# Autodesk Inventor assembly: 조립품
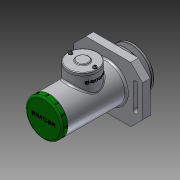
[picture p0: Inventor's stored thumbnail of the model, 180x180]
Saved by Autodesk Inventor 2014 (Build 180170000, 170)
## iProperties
Created: 2017-10
Part Number: 조립품
Document SubType Name: Assembly
Designer: NET
Author: NET
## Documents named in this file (20)
- C:\Users\NET\Desktop\471007V1020\조립품.iam
- C:\Users\NET\Desktop\471007V1020\본체.ipt
- C:\Users\NET\Desktop\471007V1020\사이드 커버.ipt
- 사이드 커버.ipt
- C:\Users\NET\Desktop\471007V1020\베어링 15 x 35 x 11.ipt
- C:\Users\NET\Desktop\471007V1020\부시1.ipt
- C:\Users\NET\Desktop\471007V1020\축.ipt
- C:\Users\NET\Desktop\471007V1020\멈춤링 15 x 1.ipt
- C:\Users\NET\Desktop\471007V1020\멈춤링 35x1.6.ipt
- C:\Users\NET\Desktop\471007V1020\부시2.ipt
- C:\Users\NET\Desktop\471007V1020\와셔 10x21.ipt
- C:\Users\NET\Desktop\471007V1020\너트 M10.ipt
- C:\Users\NET\Desktop\471007V1020\키 4 x 4 x 18.ipt
- C:\Users\NET\Desktop\471007V1020\오일 실 15 25 7.ipt
- C:\Users\NET\Desktop\471007V1020\V-벨트풀리.ipt
- C:\Users\NET\Desktop\471007V1020\와셔 4x16.ipt
- C:\Users\NET\Desktop\471007V1020\볼트 M4 x 10.ipt
- C:\Users\NET\Desktop\471007V1020\탑 커버.ipt
- C:\Users\NET\Desktop\471007V1020\와셔 3x6.ipt
- C:\Users\NET\Desktop\471007V1020\십자볼트 M3 x 10.ipt
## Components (2 placed, 2 different names)
1. V-벨트풀리:1
2. ISO 4017 M4 x 10:1
